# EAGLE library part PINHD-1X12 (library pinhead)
PIN HEADER
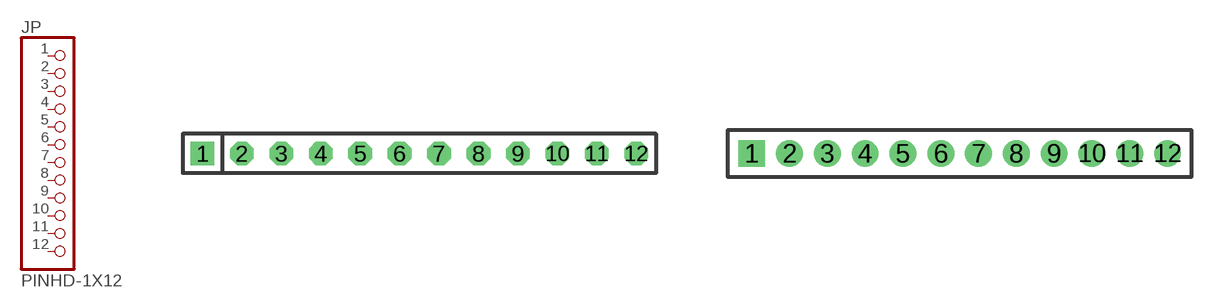
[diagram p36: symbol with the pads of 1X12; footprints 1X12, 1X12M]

Designator prefix JP

## PINHD-1X12  [1X12]
1  1  pas
2  2  pas
3  3  pas
4  4  pas
5  5  pas
6  6  pas
7  7  pas
8  8  pas
9  9  pas
10  10  pas
11  11  pas
12  12  pas

## PINHD-1X12M  [1X12M]
Pads as for 1X12

## Footprint 1X12 (pad centres in mm)
PIN HEADER - 0.1"
drill 1.016 square: 1 -13.97,0
drill 1.016 octagon: 2 -11.43,0; 3 -8.89,0; 4 -6.35,0; 5 -3.81,0; 6 -1.27,0; 7 1.27,0; 8 3.81,0; 9 6.35,0; 10 8.89,0; 11 11.43,0; 12 13.97,0

## Footprint 1X12M (pad centres in mm)
PIN HEADER - 2MM"
drill 0.914 square: 1 -11,0
drill 0.914 round: 2 -9,0; 3 -7,0; 4 -5,0; 5 -3,0; 6 -1,0; 7 1,0; 8 3,0; 9 5,0; 10 7,0; 11 9,0; 12 11,0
